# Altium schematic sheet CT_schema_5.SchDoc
size 487 x 398 mm
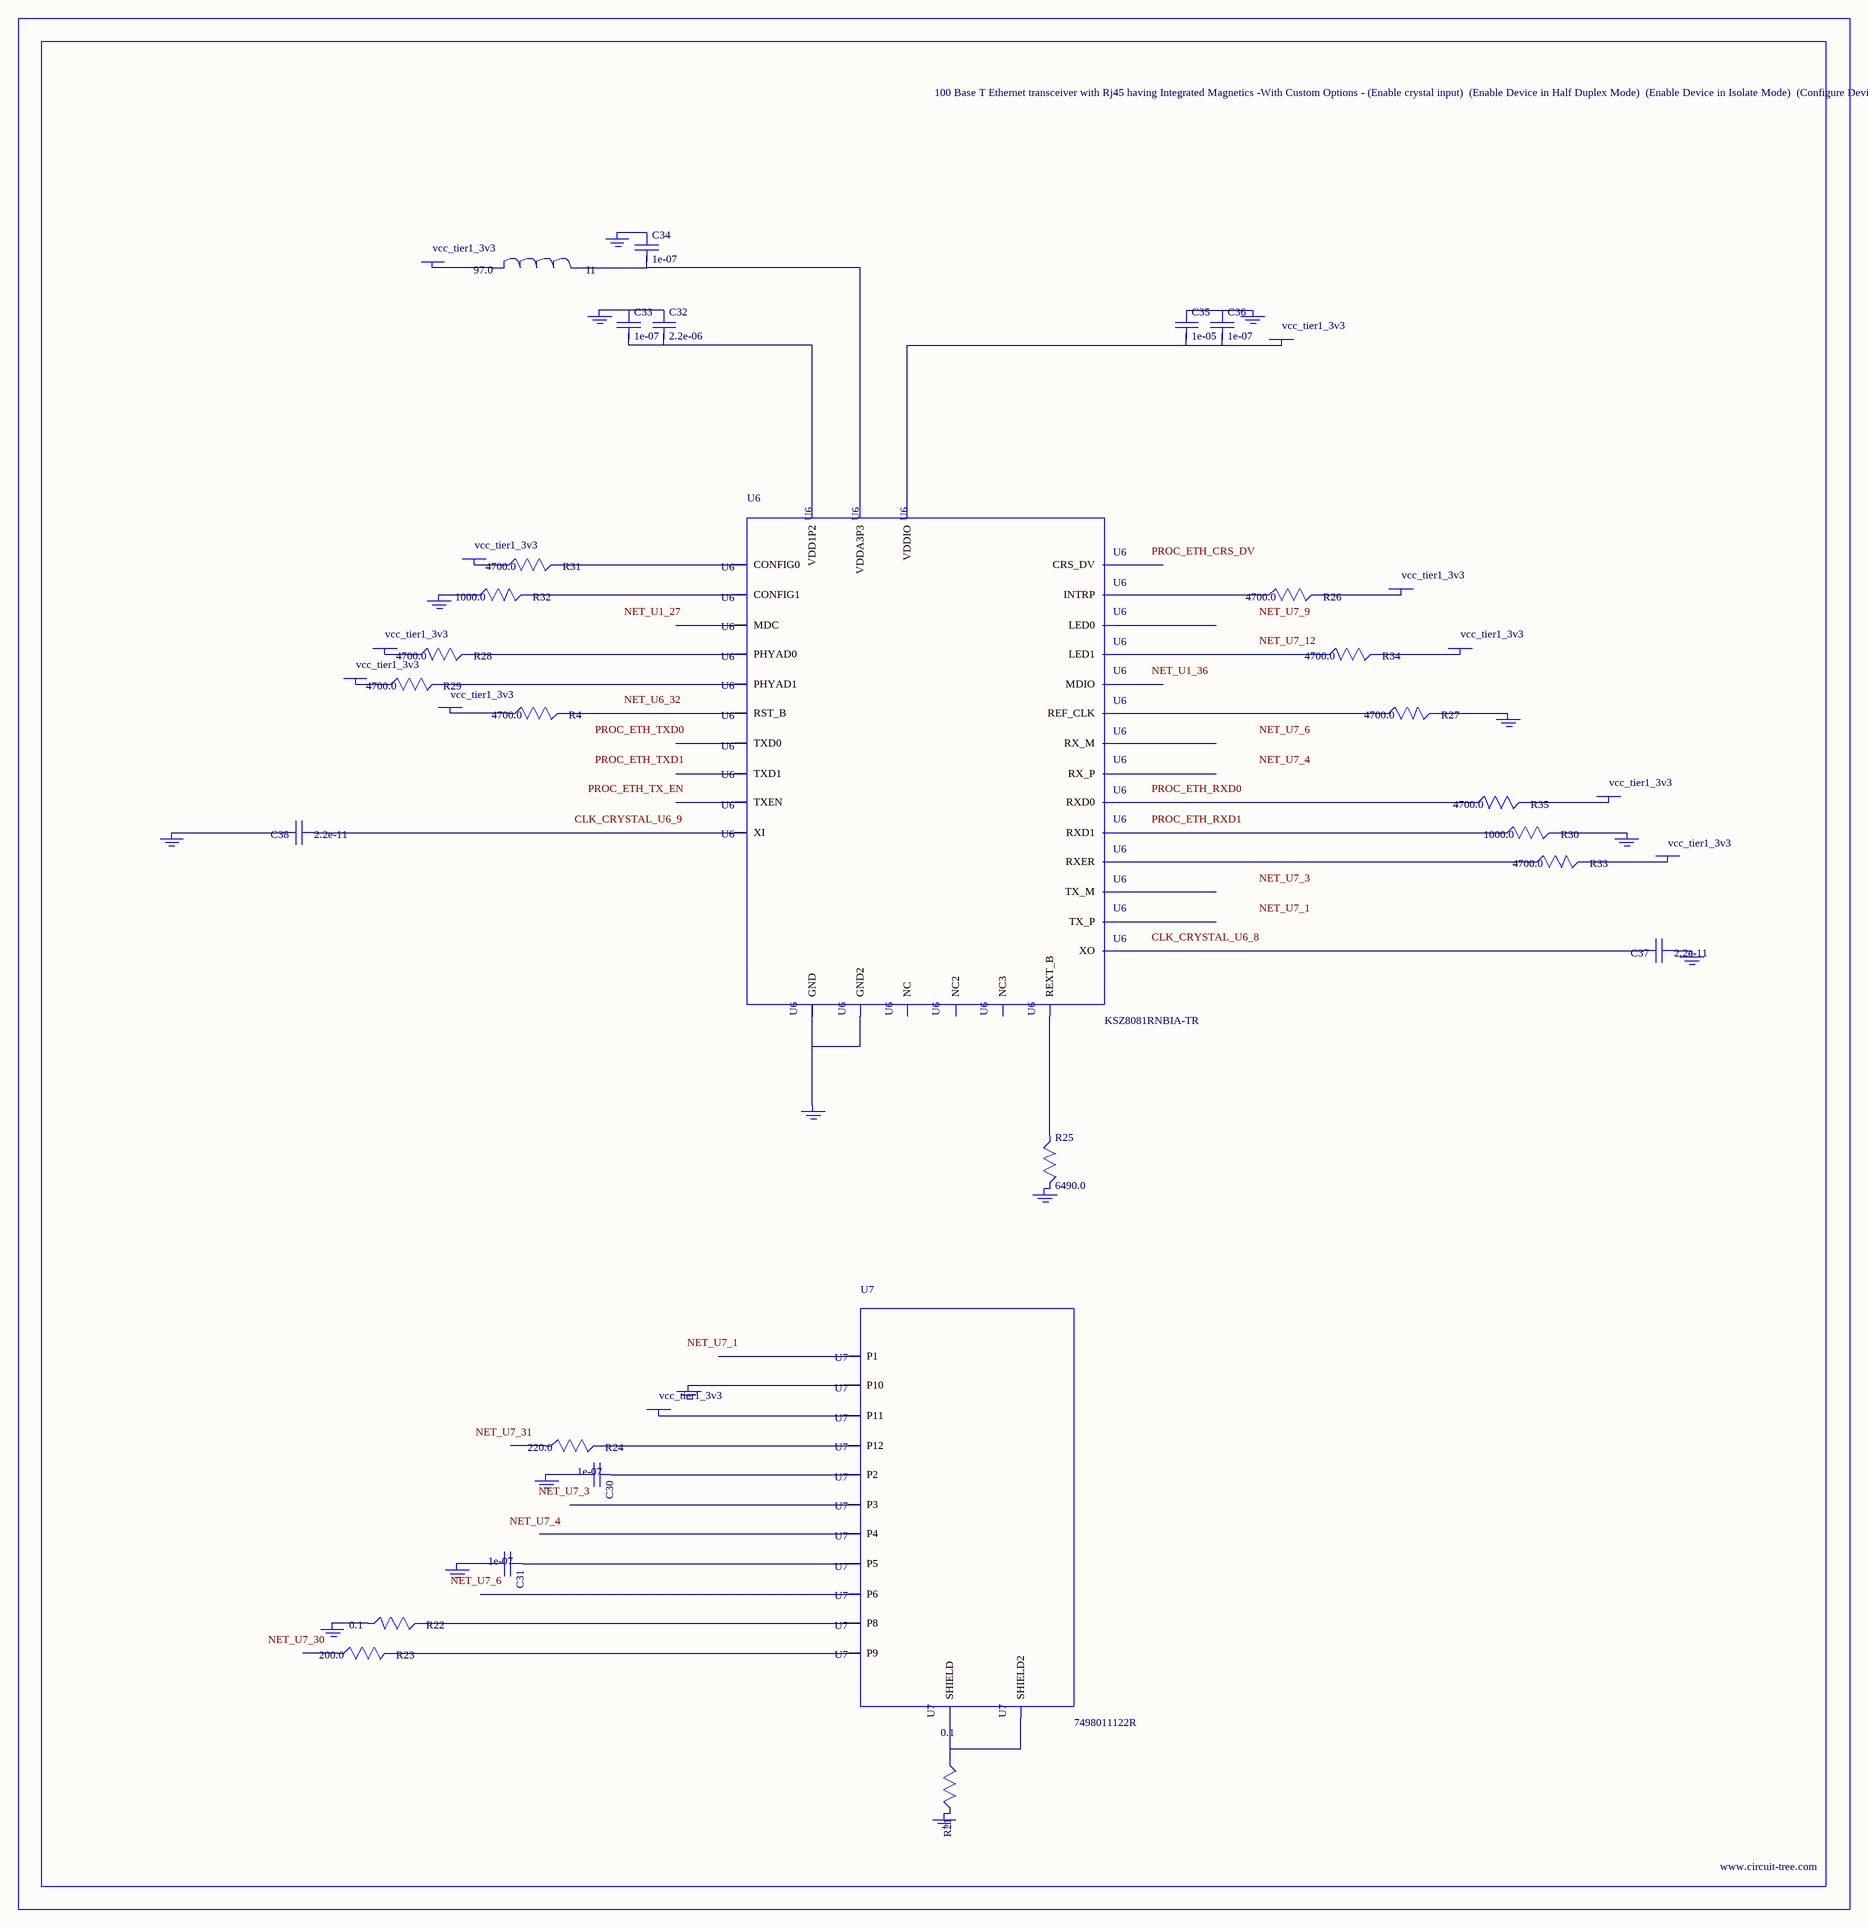
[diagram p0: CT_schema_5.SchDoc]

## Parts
BORDER4  (no value)
C30  1e-07  [C0402]
C31  1e-07  [C0402]
C32  2.2e-06  [C0603]
C33  1e-07  [C0402]
C34  1e-07  [C0402]
C35  1e-05  [C0805]
C36  1e-07  [C0402]
C37  2.2e-11  [C0402]
C38  2.2e-11  [C0402]
GND_INSTANCE_4_0  (no value)
GND_INSTANCE_4_1  (no value)
GND_INSTANCE_4_2  (no value)
GND_INSTANCE_4_3  (no value)
GND_INSTANCE_4_4  (no value)
GND_INSTANCE_4_5  (no value)
GND_INSTANCE_4_6  (no value)
GND_INSTANCE_4_7  (no value)
GND_INSTANCE_4_8  (no value)
GND_INSTANCE_4_9  (no value)
GND_INSTANCE_4_10  (no value)
GND_INSTANCE_4_11  (no value)
GND_INSTANCE_4_12  (no value)
GND_INSTANCE_4_13  (no value)
GND_INSTANCE_4_14  (no value)
I1  97.0  [R0603]
POWER_INSTANCE_4_0  vcc_tier1_3v3
POWER_INSTANCE_4_1  vcc_tier1_3v3
POWER_INSTANCE_4_2  vcc_tier1_3v3
POWER_INSTANCE_4_3  vcc_tier1_3v3
POWER_INSTANCE_4_4  vcc_tier1_3v3
POWER_INSTANCE_4_5  vcc_tier1_3v3
POWER_INSTANCE_4_6  vcc_tier1_3v3
POWER_INSTANCE_4_7  vcc_tier1_3v3
POWER_INSTANCE_4_8  vcc_tier1_3v3
POWER_INSTANCE_4_9  vcc_tier1_3v3
POWER_INSTANCE_4_10  vcc_tier1_3v3
R4  4700.0  [R0603]
R21  0.1  [R0603]
R22  0.1  [R0603]
R23  200.0  [R0603]
R24  220.0  [R0603]
R25  6490.0  [R0603]
R26  4700.0  [R0603]
R27  4700.0  [R0603]
R28  4700.0  [R0603]
R29  4700.0  [R0603]
R30  1000.0  [R0603]
R31  4700.0  [R0603]
R32  1000.0  [R0603]
R33  4700.0  [R0603]
R34  4700.0  [R0603]
R35  4700.0  [R0603]
U6  KSZ8081RNBIA-TR  [QFN-32]
U7  7498011122R  [7498011122R]

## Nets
NetC30_1: C30.1 U7.2(P2)
NetC30_2: C30.2 GND_INSTANCE_4_10.0(GND)
NetC31_1: C31.1 U7.5(P5)
NetC31_2: C31.2 GND_INSTANCE_4_11.0(GND)
NetC32_1: C32.1 C33.1 GND_INSTANCE_4_0.0(GND)
NetC32_2: C32.2 C33.2 U6.2(VDD1P2)
NetC34_1: C34.1 GND_INSTANCE_4_1.0(GND)
NetC34_2: C34.2 I1.2 U6.3(VDDA3P3)
NetC35_1: C35.1 C36.1 GND_INSTANCE_4_6.0(GND)
NetC35_2: C35.2 C36.2 POWER_INSTANCE_4_4.0(PWR) U6.17(VDDIO)
NetC37_1: C37.1 GND_INSTANCE_4_2.0(GND)
NetC37_2: C37.2 U6.8(XO)
NetC38_1: C38.1 U6.9(XI)
NetC38_2: C38.2 GND_INSTANCE_4_3.0(GND)
NetGND_INSTANCE_4_4_0: GND_INSTANCE_4_4.0(GND) R25.2
NetGND_INSTANCE_4_5_0: GND_INSTANCE_4_5.0(GND) R30.2
NetGND_INSTANCE_4_7_0: GND_INSTANCE_4_7.0(GND) R27.2
NetGND_INSTANCE_4_8_0: GND_INSTANCE_4_8.0(GND) R32.1
NetGND_INSTANCE_4_9_0: GND_INSTANCE_4_9.0(GND) U6.1(GND) U6.EXP(GND2)
NetGND_INSTANCE_4_12_0: GND_INSTANCE_4_12.0(GND) R22.1
NetGND_INSTANCE_4_13_0: GND_INSTANCE_4_13.0(GND) U7.10(P10)
NetGND_INSTANCE_4_14_0: GND_INSTANCE_4_14.0(GND) R21.2
NetI1_1: I1.1 POWER_INSTANCE_4_0.0(PWR)
NetPOWER_INSTANCE_4_1_0: POWER_INSTANCE_4_1.0(PWR) R28.1
NetPOWER_INSTANCE_4_2_0: POWER_INSTANCE_4_2.0(PWR) R29.1
NetPOWER_INSTANCE_4_3_0: POWER_INSTANCE_4_3.0(PWR) R35.2
NetPOWER_INSTANCE_4_5_0: POWER_INSTANCE_4_5.0(PWR) R33.2
NetPOWER_INSTANCE_4_6_0: POWER_INSTANCE_4_6.0(PWR) R26.2
NetPOWER_INSTANCE_4_7_0: POWER_INSTANCE_4_7.0(PWR) R31.1
NetPOWER_INSTANCE_4_8_0: POWER_INSTANCE_4_8.0(PWR) R34.2
NetPOWER_INSTANCE_4_9_0: POWER_INSTANCE_4_9.0(PWR) R4.1
NetPOWER_INSTANCE_4_10_0: POWER_INSTANCE_4_10.0(PWR) U7.11(P11)
NetR4_2: R4.2 U6.32(RST_B)
NetR21_1: R21.1 U7.13(SHIELD) U7.14(SHIELD2)
NetR22_2: R22.2 U7.8(P8)
NetR23_2: R23.2 U7.9(P9)
NetR24_2: R24.2 U7.12(P12)
NetR25_1: R25.1 U6.10(REXT_B)
NetR26_1: R26.1 U6.21(INTRP)
NetR27_1: R27.1 U6.19(REF_CLK)
NetR28_2: R28.2 U6.13(PHYAD0)
NetR29_2: R29.2 U6.14(PHYAD1)
NetR30_1: R30.1 U6.15(RXD1)
NetR31_2: R31.2 U6.28(CONFIG0)
NetR32_2: R32.2 U6.29(CONFIG1)
NetR33_1: R33.1 U6.20(RXER)
NetR34_1: R34.1 U6.31(LED1)
NetR35_1: R35.1 U6.16(RXD0)

Not connected (* = marked no-connect by the designer): R23 1; R24 1; U6 4(RX_M) 5(RX_P) 6(TX_M) 7(TX_P) 11(MDIO) 12(MDC) 18(CRS_DV) 22(NC) 23(TXEN) 24(TXD0) 25(TXD1) 26(NC2) 27(NC3) 30(LED0); U7 1(P1) 3(P3) 4(P4) 6(P6)

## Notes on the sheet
- Labels drawn without touching a wire or pin: CLK_CRYSTAL_U6_8, CLK_CRYSTAL_U6_9, NET_U1_27, NET_U1_36, NET_U6_32, NET_U7_1, NET_U7_3, NET_U7_4, NET_U7_6, NET_U7_9, NET_U7_12, NET_U7_30, NET_U7_31, PROC_ETH_CRS_DV, PROC_ETH_RXD0, PROC_ETH_RXD1, PROC_ETH_TX_EN, PROC_ETH_TXD0, PROC_ETH_TXD1

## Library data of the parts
BORDER4 = BORDER_PAGE4
C30 C31 C33 C34 C36 = C0402C104K3RACTU
C32 = C0603C225K8RACTU
C35 = C0805C106K8RACTU
C37 C38 = C0402C220K3RAC
GND_INSTANCE_4_0-GND_INSTANCE_4_14 = GND
I1 = I1
POWER_INSTANCE_4_0-POWER_INSTANCE_4_10 = PWR
R4 R26-R29 R31 R33-R35 = RC0603JR-074K7L
R21 R22 = ERJ-3RSFR10V
R23 = RC0603JR-07200RL
R24 = RC0603JR-07220RL
R25 = ERJ-3EKF6491V
R30 R32 = RC0603JR-071KL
